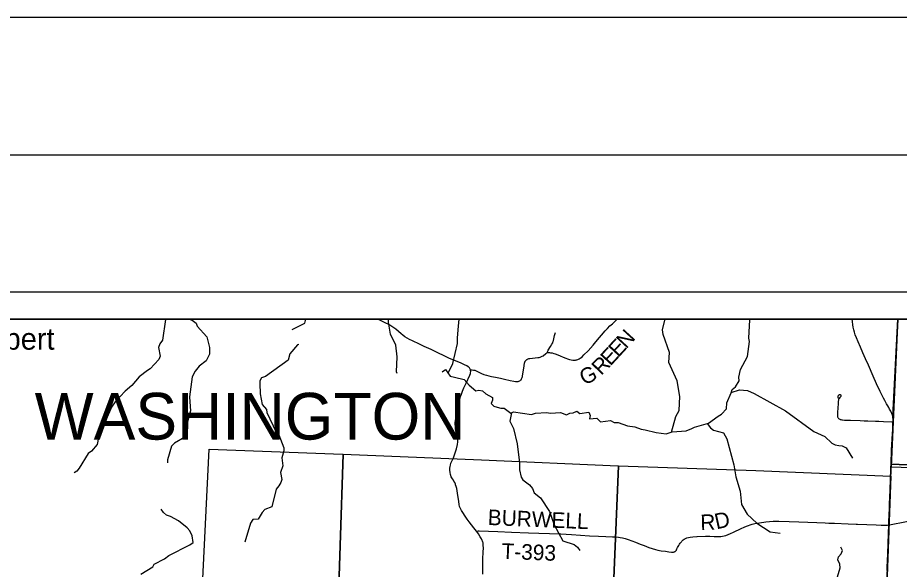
# Model space of a CAD drawing. Extents: x 0 to 34, y 0 to 22.
# Drawn here: x 2.472 to 5.686, y 19.987 to 22 of the extents above; entities that cross this region are included whole.
import ezdxf

# ---------------------------------------------------------------- set-up
doc = ezdxf.new("R2010")
doc.units = 0
for name, color, linetype in [('GM_X_County_Road', 7, 'Continuous'), ('GM_X_Minor_River', 7, 'Continuous'), ('GM_X_Rail_Line', 7, 'Continuous'), ('GM_X_Section', 7, 'Continuous'), ('GM_X_State_Route', 7, 'Continuous'), ('GM_X_Township_Road', 7, 'Continuous'), ('GM_X_Township_Road_Text', 7, 'Continuous'), ('GM_X_Township_Text', 7, 'Continuous'), ('GM_X_Unincorporated_Text', 7, 'Continuous'), ('SH_Border', 7, 'Continuous'), ('SH_Cut_Line', 7, 'Continuous'), ('SH_Data', 7, 'Continuous')]:
    doc.layers.add(name, color=color, linetype=linetype)

msp = doc.modelspace()

# ---------------------------------------------------------------- linework, layer by layer
at = {"layer": 'GM_X_County_Road'}
for points in [[(4.123, 20.7146), (4.1221, 20.7174), (4.1207, 20.72), (4.119, 20.7225), (4.117, 20.7247), (4.1147, 20.7266), (4.1095, 20.7297), (4.1012, 20.7337), (4.087, 20.7401), (4.0581, 20.7515), (4.0439, 20.7577), (4.0299, 20.7645), (4.002, 20.7783), (3.9796, 20.789), (3.9543, 20.8008), (3.9374, 20.8087), (3.9121, 20.8205), (3.9009, 20.8261), (3.8919, 20.831), (3.884, 20.8357), (3.8761, 20.8416), (3.87, 20.847), (3.8511, 20.8631), (3.8437, 20.8687), (3.8359, 20.8737), (3.8252, 20.8799), (3.8115, 20.8871), (3.7975, 20.8939), (3.7905, 20.8973), (3.7843, 20.8996), (3.7828, 20.9)], [(4.1456, 20.1259), (4.145, 20.1267), (4.1355, 20.139), (4.118, 20.1608), (4.1105, 20.1707), (4.1033, 20.1809), (4.0949, 20.1941), (4.0903, 20.2016), (4.0873, 20.2073), (4.0853, 20.2115), (4.0834, 20.2166), (4.0816, 20.2238), (4.08, 20.2349), (4.0755, 20.265), (4.0728, 20.2817), (4.0707, 20.2898), (4.0689, 20.2957), (4.0678, 20.2985), (4.0653, 20.3041), (4.0624, 20.3094), (4.0609, 20.3121), (4.0578, 20.3175), (4.0528, 20.3254), (4.0501, 20.333), (4.0484, 20.3409), (4.0479, 20.3491), (4.048, 20.3562), (4.0485, 20.3625), (4.0496, 20.3673), (4.0516, 20.3742), (4.0552, 20.3824), (4.0608, 20.3944), (4.0661, 20.4087), (4.0721, 20.4269), (4.0758, 20.4423), (4.0772, 20.452), (4.0774, 20.4592), (4.0769, 20.4658), (4.0753, 20.4723), (4.0725, 20.4813), (4.07, 20.4921), (4.0689, 20.5001), (4.0679, 20.5075), (4.0675, 20.5183), (4.0677, 20.5236), (4.0686, 20.5308), (4.0729, 20.5558), (4.0765, 20.5753), (4.0814, 20.5964), (4.0869, 20.6174), (4.0896, 20.6263), (4.0939, 20.6379), (4.0988, 20.6493), (4.1074, 20.6668), (4.1202, 20.6954), (4.1224, 20.7013), (4.1232, 20.7045), (4.1236, 20.7086), (4.1235, 20.7117), (4.123, 20.7146)], [(5.6478, 20.1492), (5.6568, 20.151), (5.7562, 20.1704)], [(4.1675, 19.9693), (4.1681, 19.9941), (4.1685, 20.0251), (4.1692, 20.05), (4.1698, 20.0655), (4.1697, 20.0747), (4.1691, 20.0808), (4.1686, 20.0838), (4.1679, 20.0868), (4.167, 20.0897), (4.166, 20.0926), (4.1634, 20.0981), (4.1588, 20.1062), (4.1522, 20.1166), (4.1456, 20.1259)]]:
    msp.add_lwpolyline(points, dxfattribs=at)
at = {"layer": 'GM_X_Minor_River'}
for points in [[(3.0114, 20.8992), (3.0003, 20.8233), (2.9901, 20.8099), (2.9864, 20.7966), (2.9919, 20.7645), (2.9867, 20.7531), (2.9555, 20.7191), (2.9457, 20.7123), (2.9152, 20.6897), (2.8886, 20.6581), (2.8641, 20.6371), (2.8273, 20.5986), (2.8149, 20.5784), (2.791, 20.5259), (2.7825, 20.5069), (2.7716, 20.4944), (2.7624, 20.4432), (2.7414, 20.4184), (2.7301, 20.41), (2.6972, 20.3567), (2.6881, 20.3457), (2.6783, 20.3399)], [(3.0974, 20.9), (3.1088, 20.8967), (3.1228, 20.8851), (3.1263, 20.8741), (3.1625, 20.8354), (3.1714, 20.7972), (3.1715, 20.7725), (3.1592, 20.7482), (3.134, 20.7283), (3.1194, 20.7108), (3.1089, 20.6892), (3.0991, 20.6167), (3.1009, 20.5811), (3.1028, 20.5652), (3.0921, 20.5254), (3.0915, 20.5008), (3.0819, 20.47), (3.0446, 20.4482), (3.0333, 20.4363), (3.0185, 20.3874), (3.0185, 20.3764)], [(3.4736, 20.8617), (3.5188, 20.8852), (3.523, 20.9)], [(3.8556, 20.7021), (3.8531, 20.7073), (3.8555, 20.7626), (3.851, 20.805), (3.8319, 20.845), (3.824, 20.8893), (3.8237, 20.9)], [(4.0192, 20.7073), (4.032, 20.7161), (4.0488, 20.692), (4.0651, 20.6887), (4.1003, 20.6802), (4.1178, 20.6592), (4.1429, 20.6381), (4.1531, 20.6408), (4.1671, 20.6383), (4.1789, 20.627), (4.2032, 20.6139), (4.2036, 20.6041), (4.1988, 20.5927), (4.2083, 20.5829), (4.2197, 20.5788), (4.233, 20.5751), (4.2451, 20.5756), (4.2701, 20.5576), (4.2799, 20.5618), (4.3454, 20.5525), (4.3605, 20.5575), (4.4002, 20.56), (4.4146, 20.5567), (4.4505, 20.5589), (4.4725, 20.5515), (4.4846, 20.5572), (4.4971, 20.5577), (4.5103, 20.5646), (4.5213, 20.556), (4.5542, 20.5608), (4.5592, 20.5487), (4.557, 20.5358), (4.5834, 20.5394), (4.5967, 20.5255), (4.6338, 20.5303), (4.6467, 20.5236), (4.6611, 20.5225), (4.6952, 20.5106), (4.7217, 20.5067), (4.7456, 20.4989), (4.76, 20.4963), (4.7994, 20.486), (4.8361, 20.4817), (4.8576, 20.4887), (4.9086, 20.4928), (4.9294, 20.5006), (4.9396, 20.5059), (4.9902, 20.5203), (5.0252, 20.5467), (5.0376, 20.5529), (5.056, 20.5723), (5.057, 20.595), (5.0727, 20.6311), (5.0768, 20.6437), (5.0892, 20.6536), (5.1023, 20.6745), (5.1011, 20.6885), (5.1066, 20.7166), (5.1328, 20.7641), (5.1396, 20.8187), (5.138, 20.8312), (5.1406, 20.8979), (5.1405, 20.9)], [(4.0411, 20.703), (4.0591, 20.7379), (4.076, 20.8108), (4.0752, 20.8323), (4.0791, 20.8748), (4.0814, 20.9)], [(4.8553, 20.488), (4.8712, 20.5452), (4.884, 20.5669), (4.8859, 20.6184), (4.8765, 20.6752), (4.8454, 20.742), (4.8486, 20.778), (4.8255, 20.8442), (4.8228, 20.8612), (4.8309, 20.8965), (4.8313, 20.9)], [(3.4979, 20.8072), (3.4928, 20.8062), (3.4647, 20.7735), (3.4584, 20.7503), (3.3755, 20.6906), (3.3616, 20.6856), (3.3556, 20.6746), (3.3549, 20.6651), (3.3559, 20.628), (3.3641, 20.589), (3.3797, 20.5702), (3.3805, 20.5592), (3.4142, 20.4875), (3.4245, 20.4781), (3.4429, 20.4309), (3.4426, 20.4199), (3.4348, 20.3941), (3.4388, 20.3653), (3.4303, 20.341), (3.4353, 20.3149), (3.4316, 20.3039), (3.4241, 20.2917), (3.4147, 20.2795), (3.3989, 20.215), (3.3732, 20.2054), (3.3631, 20.1947), (3.3492, 20.1707), (3.3296, 20.1687), (3.3217, 20.1558), (3.3009, 20.087)], [(5.0732, 20.6327), (5.104, 20.6423), (5.132, 20.6395), (5.1567, 20.6291), (5.2713, 20.5651), (5.3742, 20.4904), (5.4141, 20.4725), (5.4399, 20.4481), (5.4525, 20.4414), (5.4657, 20.4392), (5.4782, 20.4374), (5.4922, 20.4303), (5.5148, 20.3926)], [(4.272, 20.5584), (4.2661, 20.528), (4.2799, 20.5008), (4.2931, 20.4456), (4.3015, 20.3756), (4.3013, 20.3502), (4.3079, 20.3241), (4.314, 20.3136), (4.3383, 20.2959), (4.3494, 20.282), (4.3548, 20.2661), (4.3776, 20.2477), (4.4104, 20.1984), (4.4285, 20.1496), (4.4598, 20.0908), (4.5008, 20.0778), (4.5133, 20.068), (4.5217, 20.0563)], [(4.9858, 20.5191), (4.9982, 20.5033), (5.0092, 20.4951), (5.0445, 20.4855), (5.0571, 20.4632), (5.0826, 20.3683), (5.0897, 20.3248), (5.1055, 20.273), (5.1107, 20.2234), (5.1318, 20.1891), (5.1664, 20.156), (5.2154, 20.1245), (5.2517, 20.1187)], [(2.9215, 19.9692), (2.9653, 19.9968), (2.9701, 20.0063), (3.0082, 20.0259), (3.024, 20.0381), (3.0998, 20.0769), (3.1122, 20.0857), (3.1083, 20.1099), (3.1006, 20.1277), (3.0907, 20.139), (3.0584, 20.1645), (3.0299, 20.1802), (3.0152, 20.1851), (3.0038, 20.1941), (2.9961, 20.2073)], [(5.4162, 19.5024), (5.4088, 19.5463), (5.4128, 19.5672), (5.4109, 19.5774), (5.3972, 19.589), (5.3803, 19.6336), (5.3713, 19.6813), (5.3685, 19.6938), (5.359, 19.7032), (5.3395, 19.7387), (5.3484, 19.7743), (5.3653, 19.7964), (5.3893, 19.8174), (5.4107, 19.8558), (5.4368, 19.9121), (5.4574, 19.9478), (5.4703, 19.9934), (5.4687, 20.0066), (5.4622, 20.0225), (5.4648, 20.0335), (5.4742, 20.0441), (5.4794, 20.0559), (5.4733, 20.068)]]:
    msp.add_lwpolyline(points, dxfattribs=at)
at = {"layer": 'GM_X_Rail_Line'}
for points in [[(5.6412, 19.9842), (5.6417, 19.9935), (5.644, 20.0435), (5.6454, 20.0833), (5.6463, 20.1174), (5.6476, 20.1497), (5.648, 20.1614), (5.6498, 20.2109), (5.6504, 20.2297), (5.6508, 20.2455), (5.6525, 20.282), (5.6534, 20.3099), (5.654, 20.3257), (5.6546, 20.3418), (5.6553, 20.3577), (5.6557, 20.3708), (5.6562, 20.3845), (5.6571, 20.4094), (5.6576, 20.425), (5.6583, 20.4403), (5.6596, 20.4651), (5.6607, 20.4817), (5.6619, 20.4992), (5.6626, 20.5183), (5.6629, 20.5264), (5.663, 20.5305), (5.663, 20.5359), (5.6626, 20.5401), (5.6619, 20.5454), (5.68, 20.9), (2.1, 20.9)], [(8.9, 20.9), (5.68, 20.9), (5.6619, 20.5454), (5.6626, 20.5401), (5.663, 20.5359), (5.663, 20.5305), (5.6629, 20.5264), (5.6626, 20.5183), (5.6619, 20.4992), (5.6607, 20.4817), (5.6596, 20.4651), (5.6583, 20.4403), (5.6576, 20.425), (5.6571, 20.4094), (5.6562, 20.3845), (5.6557, 20.3708), (6.4497, 20.3378)], [(6.4497, 20.3378), (5.6557, 20.3708), (5.6553, 20.3577), (5.6546, 20.3418), (5.654, 20.3257), (5.6534, 20.3099), (5.6525, 20.282), (5.6508, 20.2455), (5.6504, 20.2297), (5.6498, 20.2109), (5.648, 20.1614), (5.6476, 20.1497), (5.6463, 20.1174), (5.6454, 20.0833), (5.644, 20.0435), (5.6417, 19.9935), (5.6412, 19.9842), (5.6047, 18.8149), (5.5414, 17.2599)]]:
    msp.add_lwpolyline(points, dxfattribs=at)
at = {"layer": 'GM_X_Section'}
for points in [[(3.656, 20.4072), (3.659, 20.4071), (3.6257, 19.4083), (3.1243, 19.4279), (3.1294, 19.5533), (3.1464, 19.9283), (3.1709, 20.426)], [(4.1631, 20.3865), (4.6595, 20.365), (4.6626, 20.3648), (4.6214, 19.3661), (3.6257, 19.4083), (3.659, 20.4071)], [(5.1633, 20.3473), (5.6549, 20.3275), (5.6189, 19.331), (4.6214, 19.3661), (4.6626, 20.3648)], [(5.6562, 20.3612), (6.6348, 20.3279), (6.5918, 19.2905), (5.6189, 19.331), (5.6549, 20.3275)]]:
    msp.add_lwpolyline(points, close=True, dxfattribs=at)
at = {"layer": 'GM_X_State_Route'}
for points in [[(5.6631, 20.5258), (5.6632, 20.53), (5.6632, 20.5354), (5.6629, 20.5396), (5.6621, 20.5448), (5.6605, 20.5502), (5.6581, 20.5563), (5.6544, 20.5647), (5.6504, 20.5722), (5.6471, 20.578), (5.6439, 20.5836), (5.6397, 20.5911), (5.633, 20.603), (5.6281, 20.6123), (5.6163, 20.6358), (5.6033, 20.6639), (5.5906, 20.6922), (5.5731, 20.7321), (5.563, 20.7547), (5.5531, 20.7776), (5.5444, 20.7975), (5.5356, 20.8174), (5.5296, 20.8316), (5.525, 20.8432), (5.5221, 20.8521), (5.5196, 20.8611), (5.5177, 20.8703), (5.5162, 20.8795), (5.5149, 20.8919), (5.5143, 20.9)], [(5.6478, 20.1492), (5.6483, 20.1609), (5.65, 20.2104), (5.6506, 20.2292), (5.651, 20.2449), (5.6527, 20.2815), (5.6536, 20.3094), (5.6542, 20.3252), (5.6548, 20.3412), (5.6555, 20.3571), (5.6559, 20.3703), (5.6564, 20.384), (5.6573, 20.4088), (5.6579, 20.4245), (5.6585, 20.4397), (5.6598, 20.4646), (5.6609, 20.4812), (5.6621, 20.4987), (5.6629, 20.5177), (5.6631, 20.5258)], [(5.6414, 19.9836), (5.6419, 19.993), (5.6442, 20.0429), (5.6456, 20.0828), (5.6465, 20.1168), (5.6478, 20.1492)]]:
    msp.add_lwpolyline(points, dxfattribs=at)
at = {"layer": 'GM_X_Township_Road'}
for points in [[(4.403, 20.7778), (4.407, 20.7781), (4.411, 20.7779), (4.4141, 20.7777), (4.4172, 20.7773), (4.4202, 20.7767), (4.4262, 20.7752), (4.4321, 20.7733), (4.4407, 20.7699), (4.4493, 20.7662), (4.4604, 20.7612), (4.4704, 20.7571), (4.4765, 20.7549), (4.4839, 20.7529), (4.4899, 20.7515), (4.496, 20.7506), (4.499, 20.7505), (4.5021, 20.7505), (4.5051, 20.7509), (4.5081, 20.7514), (4.5111, 20.7521), (4.514, 20.7531), (4.5168, 20.7543), (4.5196, 20.7557), (4.5222, 20.7572), (4.5248, 20.759), (4.5296, 20.7629), (4.5363, 20.7693), (4.5515, 20.7848), (4.5701, 20.8052), (4.5801, 20.8169), (4.6137, 20.8574), (4.6222, 20.8664), (4.631, 20.8751), (4.6403, 20.8834), (4.6495, 20.8916), (4.6539, 20.896), (4.6575, 20.9)], [(4.403, 20.7778), (4.4035, 20.7807), (4.4044, 20.7835), (4.4057, 20.7863), (4.4141, 20.7998), (4.4196, 20.8084), (4.4225, 20.8138), (4.4246, 20.8194), (4.4256, 20.8225), (4.4269, 20.8286), (4.4292, 20.8398), (4.4323, 20.8517)], [(4.123, 20.7146), (4.1289, 20.7147), (4.1341, 20.7145), (4.1366, 20.7141), (4.139, 20.7136), (4.1634, 20.702), (4.172, 20.6985), (4.1809, 20.6954), (4.1899, 20.6929), (4.199, 20.6908), (4.2142, 20.6879), (4.232, 20.6845), (4.2474, 20.6816), (4.2678, 20.6767), (4.2812, 20.6738), (4.2874, 20.6727), (4.2905, 20.6725), (4.2936, 20.6725), (4.2967, 20.6729), (4.2997, 20.6738), (4.3025, 20.6751), (4.305, 20.6769), (4.3072, 20.6791), (4.3089, 20.6817), (4.3104, 20.6845), (4.3115, 20.6874), (4.3123, 20.6904), (4.313, 20.6934), (4.3172, 20.7211), (4.3204, 20.7395), (4.321, 20.7425), (4.3214, 20.7439), (4.322, 20.7454), (4.3228, 20.7469), (4.3235, 20.7481), (4.3245, 20.7495), (4.3255, 20.7505), (4.3265, 20.7516), (4.3278, 20.7525), (4.3291, 20.7533), (4.3305, 20.7541), (4.3334, 20.7552), (4.3362, 20.756), (4.3397, 20.7566), (4.3688, 20.7599), (4.3729, 20.7604), (4.3764, 20.761), (4.3796, 20.7621), (4.3821, 20.7634), (4.3848, 20.765), (4.3873, 20.7668), (4.3972, 20.7749), (4.3997, 20.7764), (4.4014, 20.7773), (4.403, 20.7778)], [(5.4632, 20.6123), (5.463, 20.6154), (5.463, 20.6171), (5.4632, 20.6188), (5.4636, 20.6205), (5.4643, 20.622), (5.4651, 20.6232), (5.4664, 20.6242), (5.4672, 20.6246), (5.4681, 20.6249), (5.469, 20.625), (5.4699, 20.6249), (5.4708, 20.6247), (5.4716, 20.6243), (5.4722, 20.6238), (5.4727, 20.623), (5.473, 20.6223), (5.4732, 20.6215), (5.4731, 20.6199), (5.4727, 20.6185), (5.4722, 20.6175), (5.4716, 20.6165), (5.4708, 20.6156), (5.4693, 20.614), (5.4664, 20.6111), (5.4654, 20.6102), (5.465, 20.6096), (5.4645, 20.6087), (5.4642, 20.6075), (5.4637, 20.6057), (5.4631, 20.5997), (5.4625, 20.5895), (5.4618, 20.5775), (5.4604, 20.5588), (5.46, 20.5526), (5.4601, 20.5495), (5.4604, 20.5462), (5.4611, 20.5432), (5.4618, 20.5412), (5.4628, 20.5397), (5.464, 20.5382), (5.4663, 20.5363), (5.4686, 20.535), (5.4704, 20.5343), (5.4725, 20.5337), (5.476, 20.5329), (5.4791, 20.5324), (5.4859, 20.5319), (5.4951, 20.5316), (5.5085, 20.5312), (5.5428, 20.53), (5.5583, 20.5294), (5.5708, 20.529), (5.5987, 20.5282), (5.6111, 20.5278), (5.6284, 20.5271), (5.6589, 20.526), (5.6631, 20.5258)], [(4.9495, 20.1072), (4.9796, 20.108), (4.9951, 20.1081), (5.0106, 20.1076), (5.026, 20.1071), (5.0353, 20.1073), (5.0415, 20.1079), (5.0475, 20.1091), (5.0534, 20.1108), (5.0622, 20.114), (5.0707, 20.1176), (5.082, 20.1227), (5.1098, 20.1358), (5.1203, 20.141), (5.1294, 20.1451), (5.136, 20.1478), (5.142, 20.15), (5.1495, 20.1521), (5.1595, 20.1544), (5.1759, 20.1573), (5.1991, 20.1606), (5.2126, 20.162), (5.226, 20.1629), (5.2469, 20.1635), (5.2847, 20.1621), (5.3201, 20.1605), (5.3853, 20.1579), (5.4162, 20.1567), (5.4286, 20.1563), (5.4317, 20.1563), (5.4378, 20.1562), (5.4501, 20.1556), (5.4995, 20.1529), (5.5286, 20.1518)], [(5.5286, 20.1518), (5.5336, 20.1516), (5.6018, 20.1497), (5.6199, 20.1487), (5.6358, 20.1482), (5.6388, 20.1482), (5.6429, 20.1485), (5.6478, 20.1492)], [(4.1456, 20.1259), (4.149, 20.1267), (4.1524, 20.1275), (4.1548, 20.1277), (4.2226, 20.125), (4.2723, 20.1229), (4.3346, 20.12), (4.449, 20.1165), (4.4525, 20.1163), (4.4905, 20.1139), (4.5568, 20.1101), (4.59, 20.1079), (4.6165, 20.1067), (4.6409, 20.106), (4.6527, 20.1056), (4.6619, 20.1048), (4.668, 20.104), (4.6772, 20.1021), (4.6862, 20.0998), (4.698, 20.096), (4.7242, 20.0864), (4.7416, 20.0796), (4.756, 20.0739), (4.7734, 20.0673), (4.7851, 20.0633), (4.797, 20.0599), (4.8061, 20.0577), (4.8183, 20.0553), (4.8336, 20.0531), (4.8459, 20.0516), (4.8552, 20.0504), (4.8585, 20.0502), (4.8615, 20.0502), (4.863, 20.0503), (4.8649, 20.0507), (4.8664, 20.0512), (4.8677, 20.052), (4.869, 20.0527), (4.8701, 20.0536), (4.8712, 20.0547), (4.8724, 20.056), (4.8732, 20.0571), (4.8741, 20.0585), (4.8756, 20.0617), (4.8776, 20.0665), (4.8796, 20.0703), (4.8821, 20.0749), (4.8846, 20.0789), (4.8876, 20.0833), (4.8915, 20.0881), (4.8937, 20.0903), (4.8984, 20.0944), (4.9017, 20.0969), (4.9062, 20.0994), (4.9089, 20.1008), (4.9118, 20.1019), (4.9178, 20.1037), (4.9238, 20.105), (4.9331, 20.1062), (4.9485, 20.1071), (4.9495, 20.1072)]]:
    msp.add_lwpolyline(points, dxfattribs=at)
at = {"layer": 'GM_X_Unincorporated_Text'}
msp.add_lwpolyline([(6.6618, 20.9), (5.6806, 20.9), (5.6772, 20.825), (5.6562, 20.3612), (6.6348, 20.3279)], close=True, dxfattribs=at)
at = {"layer": 'SH_Border'}
msp.add_lwpolyline([(1.5, 21.5), (33.5, 21.5), (33.5, 0.5), (1.5, 0.5)], close=True, dxfattribs=at)
at = {"layer": 'SH_Cut_Line'}
msp.add_lwpolyline([(0, 0), (34, 0), (34, 22), (0, 22)], close=True, dxfattribs=at)
at = {"layer": 'SH_Data'}
for p, q in [((2, 21), (9, 21)), ((2.1, 20.9), (8.9, 20.9))]:
    msp.add_line(p, q, dxfattribs=at)

# ---------------------------------------------------------------- texts
at = {"layer": 'GM_X_Township_Road_Text'}
for s, height, rotation, p in [('N', 0.0568, 47.462, (4.6905, 20.7895)), ('E', 0.0568, 47.3568, (4.6616, 20.7581)), ('E', 0.0568, 47.2677, (4.6327, 20.7268)), ('R', 0.0568, 46.1656, (4.5996, 20.6923)), ('G', 0.0568, 26.6709, (4.538, 20.6574)), ('BURWELL', 0.05682, 357.5902, (4.1851, 20.1493)), ('R', 0.0568, 1.6473, (4.9614, 20.1302)), ('D', 0.0568, 12.511, (5.0195, 20.133)), ('T-393', 0.05682, 357.7515, (4.2352, 20.026))]:
    msp.add_text(s, height=height, rotation=rotation, dxfattribs=at).set_placement(p)
at = {"layer": 'GM_X_Township_Text'}
msp.add_text('WASHINGTON', height=0.17045, rotation=0, dxfattribs=at).set_placement((2.5344, 20.4607))
at = {"layer": 'GM_X_Unincorporated_Text'}
msp.add_text('Gilbert', height=0.07898, rotation=0, dxfattribs=at).set_placement((2.2959, 20.7886))

doc.saveas('drawing.dxf')
